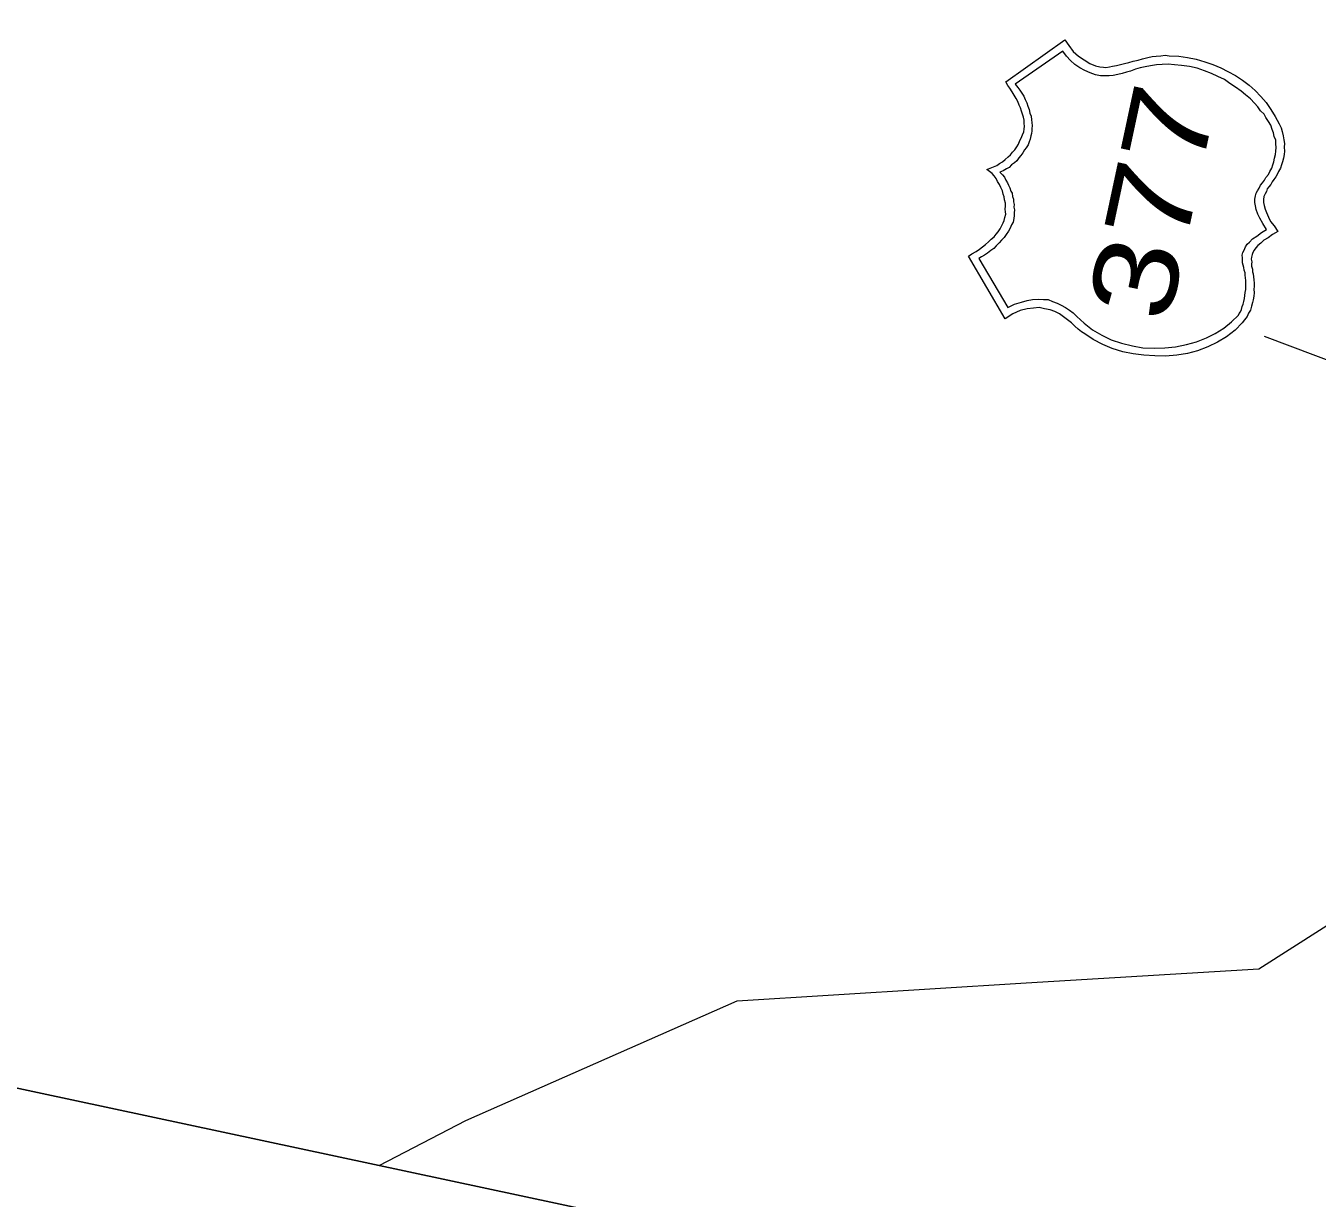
# Model space of a CAD drawing. Extents: x 2363411 to 2369126, y 6976878 to 6988319.
# Drawn here: x 2368295.3 to 2368374.1, y 6987786.2 to 6987857.8 of the extents above; entities that cross this region are included whole.
import ezdxf

# ---------------------------------------------------------------- set-up
doc = ezdxf.new("R2010")
doc.units = 0
doc.header["$LTSCALE"] = 2
doc.layers.add('62', color=7, linetype='Continuous', lineweight=13)
doc.layers.add('63', color=7, linetype='Continuous', lineweight=13)

msp = doc.modelspace()

# ---------------------------------------------------------------- linework, layer by layer
at = {"layer": '62', "lineweight": 25}
msp.add_lwpolyline([(2368004.774, 6987854.862), (2368459.776, 6987757.642), (2368553.719, 6988197.31), (2368098.715, 6988294.53)], dxfattribs=at)
at = {"layer": '62'}
for points in [[(2368355.078, 6987839.909), (2368352.834, 6987843.724), (2368353.048, 6987843.863), (2368353.31, 6987844.013), (2368353.501, 6987844.157), (2368353.694, 6987844.299), (2368353.885, 6987844.443), (2368354.06, 6987844.614), (2368354.228, 6987844.762), (2368354.4, 6987844.909), (2368354.525, 6987845.067), (2368354.649, 6987845.224), (2368354.779, 6987845.401), (2368354.861, 6987845.57), (2368354.947, 6987845.758), (2368355.023, 6987845.903), (2368355.067, 6987846.1), (2368355.109, 6987846.298), (2368355.093, 6987846.44), (2368355.082, 6987846.604), (2368355.097, 6987846.785), (2368355.092, 6987846.97), (2368355.041, 6987847.165), (2368355.012, 6987847.355), (2368354.959, 6987847.526), (2368354.909, 6987847.721), (2368354.813, 6987847.928), (2368354.735, 6987848.106), (2368354.614, 6987848.291), (2368354.537, 6987848.469), (2368354.413, 6987848.635), (2368354.281, 6987848.776), (2368354.125, 6987848.901), (2368353.967, 6987849.029), (2368354.167, 6987849.1), (2368354.37, 6987849.194), (2368354.57, 6987849.266), (2368354.736, 6987849.394), (2368354.919, 6987849.492), (2368355.086, 6987849.64), (2368355.258, 6987849.788), (2368355.4, 6987849.917), (2368355.524, 6987850.076), (2368355.674, 6987850.231), (2368355.781, 6987850.414), (2368355.886, 6987850.574), (2368355.976, 6987850.788), (2368356.054, 6987850.931), (2368356.143, 6987851.141), (2368356.209, 6987851.333), (2368356.241, 6987851.488), (2368356.256, 6987851.667), (2368356.247, 6987851.83), (2368356.245, 6987852.041), (2368356.189, 6987852.213), (2368356.139, 6987852.407), (2368356.083, 6987852.581), (2368356.01, 6987852.781), (2368355.933, 6987852.957), (2368355.844, 6987853.184), (2368355.745, 6987853.367), (2368355.629, 6987853.574), (2368355.507, 6987853.763), (2368355.373, 6987853.997), (2368355.249, 6987854.162), (2368355.11, 6987854.376), (2368358.717, 6987856.943), (2368358.965, 6987856.589), (2368359.233, 6987856.233), (2368359.565, 6987855.954), (2368359.907, 6987855.721), (2368360.254, 6987855.508), (2368360.591, 6987855.366), (2368360.851, 6987855.288), (2368361.075, 6987855.265), (2368361.234, 6987855.254), (2368361.452, 6987855.299), (2368361.639, 6987855.327), (2368361.881, 6987855.367), (2368362.127, 6987855.431), (2368362.369, 6987855.496), (2368362.634, 6987855.554), (2368362.904, 6987855.633), (2368363.198, 6987855.707), (2368363.467, 6987855.789), (2368363.783, 6987855.858), (2368364.047, 6987855.917), (2368364.307, 6987855.953), (2368364.585, 6987855.963), (2368364.848, 6987855.999), (2368365.095, 6987855.969), (2368365.684, 6987855.937), (2368366.222, 6987855.867), (2368366.749, 6987855.754), (2368367.268, 6987855.596), (2368367.766, 6987855.445), (2368368.247, 6987855.226), (2368368.684, 6987855.018), (2368369.137, 6987854.759), (2368369.564, 6987854.486), (2368369.978, 6987854.167)], [(2368370.504, 6987852.858), (2368370.297, 6987853.086), (2368370.054, 6987853.345), (2368369.761, 6987853.591), (2368369.488, 6987853.811), (2368369.145, 6987854.046), (2368368.806, 6987854.28), (2368368.465, 6987854.512), (2368368.068, 6987854.714), (2368367.67, 6987854.891), (2368367.243, 6987855.05), (2368366.795, 6987855.215), (2368366.333, 6987855.312), (2368365.84, 6987855.374), (2368365.412, 6987855.416), (2368365.03, 6987855.455), (2368364.659, 6987855.442), (2368364.311, 6987855.425), (2368363.953, 6987855.364), (2368363.637, 6987855.292), (2368363.327, 6987855.242), (2368363.03, 6987855.146), (2368362.729, 6987855.026), (2368362.487, 6987854.961), (2368362.216, 6987854.882), (2368361.95, 6987854.825), (2368361.684, 6987854.765), (2368361.426, 6987854.753), (2368361.17, 6987854.738), (2368360.896, 6987854.749), (2368360.588, 6987854.815), (2368360.266, 6987854.931), (2368359.951, 6987855.068), (2368359.639, 6987855.226), (2368359.339, 6987855.43), (2368359.073, 6987855.691), (2368358.828, 6987855.952), (2368358.595, 6987856.255), (2368355.699, 6987854.227), (2368355.842, 6987854.035), (2368355.969, 6987853.869), (2368356.089, 6987853.684), (2368356.21, 6987853.497), (2368356.306, 6987853.294), (2368356.4, 6987853.088), (2368356.471, 6987852.891), (2368356.543, 6987852.689), (2368356.589, 6987852.473), (2368356.661, 6987852.273), (2368356.686, 6987852.059), (2368356.698, 6987851.897), (2368356.72, 6987851.686), (2368356.71, 6987851.527), (2368356.703, 6987851.389), (2368356.691, 6987851.23), (2368356.639, 6987851.082), (2368356.596, 6987850.882), (2368356.535, 6987850.711), (2368356.475, 6987850.54), (2368356.368, 6987850.356), (2368356.268, 6987850.216), (2368356.159, 6987850.033), (2368356.034, 6987849.876), (2368355.913, 6987849.74), (2368355.782, 6987849.559), (2368355.64, 6987849.43), (2368355.475, 6987849.304), (2368355.327, 6987849.151), (2368355.15, 6987849.075), (2368354.964, 6987848.953), (2368354.76, 6987848.857), (2368354.907, 6987848.689), (2368355.037, 6987848.547), (2368355.115, 6987848.368), (2368355.219, 6987848.209), (2368355.277, 6987848.058), (2368355.359, 6987847.903), (2368355.432, 6987847.701), (2368355.496, 6987847.571), (2368355.524, 6987847.383), (2368355.579, 6987847.21), (2368355.593, 6987847.047), (2368355.624, 6987846.879), (2368355.612, 6987846.718), (2368355.647, 6987846.553), (2368355.633, 6987846.372), (2368355.621, 6987846.213), (2368355.604, 6987846.033), (2368355.557, 6987845.812), (2368355.475, 6987845.645), (2368355.384, 6987845.435), (2368355.277, 6987845.252), (2368355.141, 6987845.049), (2368355.011, 6987844.871), (2368354.863, 6987844.718), (2368354.71, 6987844.542), (2368354.533, 6987844.353), (2368354.384, 6987844.199), (2368354.198, 6987844.077), (2368354.001, 6987843.913), (2368353.815, 6987843.791)], [(2368369.978, 6987854.167), (2368370.35, 6987853.858), (2368370.683, 6987853.486), (2368371.018, 6987853.118), (2368371.294, 6987852.689), (2368371.571, 6987852.262), (2368371.822, 6987851.817), (2368371.929, 6987851.563), (2368371.996, 6987851.343), (2368372.054, 6987851.077), (2368372.097, 6987850.838), (2368372.141, 6987850.622), (2368372.115, 6987850.397), (2368372.13, 6987850.14), (2368372.111, 6987849.937), (2368372.085, 6987849.714), (2368372.017, 6987849.497), (2368371.952, 6987849.305), (2368371.888, 6987849.112), (2368371.774, 6987848.905), (2368371.72, 6987848.755), (2368371.613, 6987848.571), (2368371.485, 6987848.415), (2368371.386, 6987848.274), (2368371.307, 6987848.109), (2368371.186, 6987847.974), (2368371.087, 6987847.835), (2368371.031, 6987847.684), (2368370.954, 6987847.538), (2368370.872, 6987847.372), (2368370.856, 6987847.191), (2368370.862, 6987847.006), (2368370.89, 6987846.816), (2368370.958, 6987846.593), (2368371.032, 6987846.393), (2368371.156, 6987846.115), (2368371.284, 6987845.856), (2368371.502, 6987845.581), (2368371.726, 6987845.232), (2368371.412, 6987845.048), (2368371.139, 6987844.852), (2368370.878, 6987844.702), (2368370.702, 6987844.531), (2368370.51, 6987844.388), (2368370.385, 6987844.232), (2368370.286, 6987844.092), (2368370.209, 6987843.947), (2368370.163, 6987843.842), (2368370.125, 6987843.666), (2368370.103, 6987843.554), (2368370.135, 6987843.388), (2368370.13, 6987843.25), (2368370.123, 6987843.114), (2368370.178, 6987842.943), (2368370.188, 6987842.775), (2368370.232, 6987842.653), (2368370.237, 6987842.468), (2368370.268, 6987842.278), (2368370.295, 6987842.09), (2368370.276, 6987841.885), (2368370.258, 6987841.705), (2368370.282, 6987841.491), (2368370.262, 6987841.291), (2368370.217, 6987841.07), (2368370.177, 6987840.894), (2368370.13, 6987840.673), (2368370.058, 6987840.435), (2368369.948, 6987840.252), (2368369.858, 6987840.042), (2368369.701, 6987839.844), (2368369.545, 6987839.649), (2368369.128, 6987839.208), (2368368.603, 6987838.813), (2368368.05, 6987838.471), (2368367.459, 6987838.184), (2368366.834, 6987837.95), (2368366.223, 6987837.781), (2368365.559, 6987837.692), (2368364.88, 6987837.631), (2368364.213, 6987837.636), (2368363.557, 6987837.682), (2368362.903, 6987837.755), (2368362.265, 6987837.891), (2368361.62, 6987838.096), (2368361.049, 6987838.335), (2368360.449, 6987838.647), (2368359.945, 6987838.982), (2368359.746, 6987839.118), (2368359.527, 6987839.28), (2368359.335, 6987839.458), (2368359.126, 6987839.666), (2368358.884, 6987839.832), (2368358.648, 6987840.02), (2368358.389, 6987840.214), (2368358.118, 6987840.342), (2368357.817, 6987840.451), (2368357.488, 6987840.521), (2368357.157, 6987840.594), (2368356.803, 6987840.553), (2368356.426, 6987840.519), (2368355.99, 6987840.404)], [(2368353.472, 6987843.59), (2368355.245, 6987840.587), (2368355.658, 6987840.798), (2368356.076, 6987840.915), (2368356.423, 6987841.025), (2368356.757, 6987841.093), (2368357.106, 6987841.11), (2368357.424, 6987841.087), (2368357.698, 6987841.075), (2368357.976, 6987840.971), (2368358.252, 6987840.865), (2368358.502, 6987840.742), (2368358.772, 6987840.592), (2368359.011, 6987840.427), (2368359.23, 6987840.264), (2368359.461, 6987840.053), (2368359.67, 6987839.85), (2368359.901, 6987839.638), (2368360.414, 6987839.229), (2368360.986, 6987838.901), (2368361.548, 6987838.619), (2368362.192, 6987838.412), (2368362.847, 6987838.249), (2368363.493, 6987838.134), (2368364.174, 6987838.103), (2368364.823, 6987838.124), (2368365.481, 6987838.192), (2368366.155, 6987838.326), (2368366.766, 6987838.492), (2368367.37, 6987838.733), (2368367.911, 6987839.008), (2368368.44, 6987839.33), (2368368.891, 6987839.721), (2368369.325, 6987840.131), (2368369.37, 6987840.238), (2368369.46, 6987840.335), (2368369.514, 6987840.481), (2368369.554, 6987840.659), (2368369.608, 6987840.807), (2368369.662, 6987840.957), (2368369.7, 6987841.135), (2368369.719, 6987841.335), (2368369.736, 6987841.518), (2368369.773, 6987841.692), (2368369.767, 6987841.879), (2368369.782, 6987842.058), (2368369.776, 6987842.244), (2368369.764, 6987842.408), (2368369.732, 6987842.576), (2368369.739, 6987842.712), (2368369.682, 6987842.885), (2368369.645, 6987843.032), (2368369.608, 6987843.177), (2368369.571, 6987843.324), (2368369.564, 6987843.51), (2368369.564, 6987843.624), (2368369.554, 6987843.788), (2368369.592, 6987843.964), (2368369.667, 6987844.107), (2368369.755, 6987844.297), (2368369.859, 6987844.459), (2368370.001, 6987844.59), (2368370.18, 6987844.783), (2368370.448, 6987844.955), (2368370.723, 6987845.17), (2368371.038, 6987845.357), (2368370.819, 6987845.727), (2368370.633, 6987846.042), (2368370.504, 6987846.299), (2368370.402, 6987846.574), (2368370.361, 6987846.812), (2368370.333, 6987847.002), (2368370.332, 6987847.211), (2368370.373, 6987847.409), (2368370.411, 6987847.587), (2368370.488, 6987847.73), (2368370.592, 6987847.892), (2368370.673, 6987848.059), (2368370.799, 6987848.216), (2368370.926, 6987848.373), (2368371.006, 6987848.54), (2368371.159, 6987848.714), (2368371.244, 6987848.904), (2368371.36, 6987849.11), (2368371.424, 6987849.303), (2368371.487, 6987849.494), (2368371.533, 6987849.715), (2368371.581, 6987849.936), (2368371.603, 6987850.14), (2368371.626, 6987850.364), (2368371.608, 6987850.597), (2368371.606, 6987850.806), (2368371.515, 6987851.032), (2368371.474, 6987851.27), (2368371.381, 6987851.476), (2368371.296, 6987851.723), (2368371.161, 6987851.959), (2368371.007, 6987852.198), (2368370.889, 6987852.409), (2368370.68, 6987852.616), (2368370.504, 6987852.858)], [(2368316.854, 6987788.182), (2368322.138, 6987790.941), (2368338.721, 6987798.237), (2368356.354, 6987799.347), (2368370.57, 6987800.198), (2368380.507, 6987806.541), (2368397.068, 6987818.558), (2368405.207, 6987825.955), (2368418.347, 6987837.711), (2368437.149, 6987845.475)], [(2368353.815, 6987843.791), (2368353.632, 6987843.693), (2368353.472, 6987843.59)], [(2368355.99, 6987840.404), (2368355.554, 6987840.2), (2368355.078, 6987839.909)], [(2368370.893, 6987838.853), (2368383.263, 6987834.188), (2368395.397, 6987828.188), (2368404.391, 6987814.277), (2368413.364, 6987797.381), (2368426.436, 6987777.677), (2368432.622, 6987763.444)]]:
    msp.add_lwpolyline(points, dxfattribs=at)
at = {"layer": '63', "lineweight": 25}
msp.add_lwpolyline([(2368004.774, 6987854.862), (2368459.776, 6987757.642), (2368553.719, 6988197.31), (2368098.715, 6988294.53)], dxfattribs=at)
at = {"layer": '63'}
for points in [[(2368355.078, 6987839.909), (2368352.834, 6987843.724), (2368353.048, 6987843.863), (2368353.31, 6987844.013), (2368353.501, 6987844.157), (2368353.694, 6987844.299), (2368353.885, 6987844.443), (2368354.06, 6987844.614), (2368354.228, 6987844.762), (2368354.4, 6987844.909), (2368354.525, 6987845.067), (2368354.649, 6987845.224), (2368354.779, 6987845.401), (2368354.861, 6987845.57), (2368354.947, 6987845.758), (2368355.023, 6987845.903), (2368355.067, 6987846.1), (2368355.109, 6987846.298), (2368355.093, 6987846.44), (2368355.082, 6987846.604), (2368355.097, 6987846.785), (2368355.092, 6987846.97), (2368355.041, 6987847.165), (2368355.012, 6987847.355), (2368354.959, 6987847.526), (2368354.909, 6987847.721), (2368354.813, 6987847.928), (2368354.735, 6987848.106), (2368354.614, 6987848.291), (2368354.537, 6987848.469), (2368354.413, 6987848.635), (2368354.281, 6987848.776), (2368354.125, 6987848.901), (2368353.967, 6987849.029), (2368354.167, 6987849.1), (2368354.37, 6987849.194), (2368354.57, 6987849.266), (2368354.736, 6987849.394), (2368354.919, 6987849.492), (2368355.086, 6987849.64), (2368355.258, 6987849.788), (2368355.4, 6987849.917), (2368355.524, 6987850.076), (2368355.674, 6987850.231), (2368355.781, 6987850.414), (2368355.886, 6987850.574), (2368355.976, 6987850.788), (2368356.054, 6987850.931), (2368356.143, 6987851.141), (2368356.209, 6987851.333), (2368356.241, 6987851.488), (2368356.256, 6987851.667), (2368356.247, 6987851.83), (2368356.245, 6987852.041), (2368356.189, 6987852.213), (2368356.139, 6987852.407), (2368356.083, 6987852.581), (2368356.01, 6987852.781), (2368355.933, 6987852.957), (2368355.844, 6987853.184), (2368355.745, 6987853.367), (2368355.629, 6987853.574), (2368355.507, 6987853.763), (2368355.373, 6987853.997), (2368355.249, 6987854.162), (2368355.11, 6987854.376), (2368358.717, 6987856.943), (2368358.965, 6987856.589), (2368359.233, 6987856.233), (2368359.565, 6987855.954), (2368359.907, 6987855.721), (2368360.254, 6987855.508), (2368360.591, 6987855.366), (2368360.851, 6987855.288), (2368361.075, 6987855.265), (2368361.234, 6987855.254), (2368361.452, 6987855.299), (2368361.639, 6987855.327), (2368361.881, 6987855.367), (2368362.127, 6987855.431), (2368362.369, 6987855.496), (2368362.634, 6987855.554), (2368362.904, 6987855.633), (2368363.198, 6987855.707), (2368363.467, 6987855.789), (2368363.783, 6987855.858), (2368364.047, 6987855.917), (2368364.307, 6987855.953), (2368364.585, 6987855.963), (2368364.848, 6987855.999), (2368365.095, 6987855.969), (2368365.684, 6987855.937), (2368366.222, 6987855.867), (2368366.749, 6987855.754), (2368367.268, 6987855.596), (2368367.766, 6987855.445), (2368368.247, 6987855.226), (2368368.684, 6987855.018), (2368369.137, 6987854.759), (2368369.564, 6987854.486), (2368369.978, 6987854.167)], [(2368370.504, 6987852.858), (2368370.297, 6987853.086), (2368370.054, 6987853.345), (2368369.761, 6987853.591), (2368369.488, 6987853.811), (2368369.145, 6987854.046), (2368368.806, 6987854.28), (2368368.465, 6987854.512), (2368368.068, 6987854.714), (2368367.67, 6987854.891), (2368367.243, 6987855.05), (2368366.795, 6987855.215), (2368366.333, 6987855.312), (2368365.84, 6987855.374), (2368365.412, 6987855.416), (2368365.03, 6987855.455), (2368364.659, 6987855.442), (2368364.311, 6987855.425), (2368363.953, 6987855.364), (2368363.637, 6987855.292), (2368363.327, 6987855.242), (2368363.03, 6987855.146), (2368362.729, 6987855.026), (2368362.487, 6987854.961), (2368362.216, 6987854.882), (2368361.95, 6987854.825), (2368361.684, 6987854.765), (2368361.426, 6987854.753), (2368361.17, 6987854.738), (2368360.896, 6987854.749), (2368360.588, 6987854.815), (2368360.266, 6987854.931), (2368359.951, 6987855.068), (2368359.639, 6987855.226), (2368359.339, 6987855.43), (2368359.073, 6987855.691), (2368358.828, 6987855.952), (2368358.595, 6987856.255), (2368355.699, 6987854.227), (2368355.842, 6987854.035), (2368355.969, 6987853.869), (2368356.089, 6987853.684), (2368356.21, 6987853.497), (2368356.306, 6987853.294), (2368356.4, 6987853.088), (2368356.471, 6987852.891), (2368356.543, 6987852.689), (2368356.589, 6987852.473), (2368356.661, 6987852.273), (2368356.686, 6987852.059), (2368356.698, 6987851.897), (2368356.72, 6987851.686), (2368356.71, 6987851.527), (2368356.703, 6987851.389), (2368356.691, 6987851.23), (2368356.639, 6987851.082), (2368356.596, 6987850.882), (2368356.535, 6987850.711), (2368356.475, 6987850.54), (2368356.368, 6987850.356), (2368356.268, 6987850.216), (2368356.159, 6987850.033), (2368356.034, 6987849.876), (2368355.913, 6987849.74), (2368355.782, 6987849.559), (2368355.64, 6987849.43), (2368355.475, 6987849.304), (2368355.327, 6987849.151), (2368355.15, 6987849.075), (2368354.964, 6987848.953), (2368354.76, 6987848.857), (2368354.907, 6987848.689), (2368355.037, 6987848.547), (2368355.115, 6987848.368), (2368355.219, 6987848.209), (2368355.277, 6987848.058), (2368355.359, 6987847.903), (2368355.432, 6987847.701), (2368355.496, 6987847.571), (2368355.524, 6987847.383), (2368355.579, 6987847.21), (2368355.593, 6987847.047), (2368355.624, 6987846.879), (2368355.612, 6987846.718), (2368355.647, 6987846.553), (2368355.633, 6987846.372), (2368355.621, 6987846.213), (2368355.604, 6987846.033), (2368355.557, 6987845.812), (2368355.475, 6987845.645), (2368355.384, 6987845.435), (2368355.277, 6987845.252), (2368355.141, 6987845.049), (2368355.011, 6987844.871), (2368354.863, 6987844.718), (2368354.71, 6987844.542), (2368354.533, 6987844.353), (2368354.384, 6987844.199), (2368354.198, 6987844.077), (2368354.001, 6987843.913), (2368353.815, 6987843.791)], [(2368369.978, 6987854.167), (2368370.35, 6987853.858), (2368370.683, 6987853.486), (2368371.018, 6987853.118), (2368371.294, 6987852.689), (2368371.571, 6987852.262), (2368371.822, 6987851.817), (2368371.929, 6987851.563), (2368371.996, 6987851.343), (2368372.054, 6987851.077), (2368372.097, 6987850.838), (2368372.141, 6987850.622), (2368372.115, 6987850.397), (2368372.13, 6987850.14), (2368372.111, 6987849.937), (2368372.085, 6987849.714), (2368372.017, 6987849.497), (2368371.952, 6987849.305), (2368371.888, 6987849.112), (2368371.774, 6987848.905), (2368371.72, 6987848.755), (2368371.613, 6987848.571), (2368371.485, 6987848.415), (2368371.386, 6987848.274), (2368371.307, 6987848.109), (2368371.186, 6987847.974), (2368371.087, 6987847.835), (2368371.031, 6987847.684), (2368370.954, 6987847.538), (2368370.872, 6987847.372), (2368370.856, 6987847.191), (2368370.862, 6987847.006), (2368370.89, 6987846.816), (2368370.958, 6987846.593), (2368371.032, 6987846.393), (2368371.156, 6987846.115), (2368371.284, 6987845.856), (2368371.502, 6987845.581), (2368371.726, 6987845.232), (2368371.412, 6987845.048), (2368371.139, 6987844.852), (2368370.878, 6987844.702), (2368370.702, 6987844.531), (2368370.51, 6987844.388), (2368370.385, 6987844.232), (2368370.286, 6987844.092), (2368370.209, 6987843.947), (2368370.163, 6987843.842), (2368370.125, 6987843.666), (2368370.103, 6987843.554), (2368370.135, 6987843.388), (2368370.13, 6987843.25), (2368370.123, 6987843.114), (2368370.178, 6987842.943), (2368370.188, 6987842.775), (2368370.232, 6987842.653), (2368370.237, 6987842.468), (2368370.268, 6987842.278), (2368370.295, 6987842.09), (2368370.276, 6987841.885), (2368370.258, 6987841.705), (2368370.282, 6987841.491), (2368370.262, 6987841.291), (2368370.217, 6987841.07), (2368370.177, 6987840.894), (2368370.13, 6987840.673), (2368370.058, 6987840.435), (2368369.948, 6987840.252), (2368369.858, 6987840.042), (2368369.701, 6987839.844), (2368369.545, 6987839.649), (2368369.128, 6987839.208), (2368368.603, 6987838.813), (2368368.05, 6987838.471), (2368367.459, 6987838.184), (2368366.834, 6987837.95), (2368366.223, 6987837.781), (2368365.559, 6987837.692), (2368364.88, 6987837.631), (2368364.213, 6987837.636), (2368363.557, 6987837.682), (2368362.903, 6987837.755), (2368362.265, 6987837.891), (2368361.62, 6987838.096), (2368361.049, 6987838.335), (2368360.449, 6987838.647), (2368359.945, 6987838.982), (2368359.746, 6987839.118), (2368359.527, 6987839.28), (2368359.335, 6987839.458), (2368359.126, 6987839.666), (2368358.884, 6987839.832), (2368358.648, 6987840.02), (2368358.389, 6987840.214), (2368358.118, 6987840.342), (2368357.817, 6987840.451), (2368357.488, 6987840.521), (2368357.157, 6987840.594), (2368356.803, 6987840.553), (2368356.426, 6987840.519), (2368355.99, 6987840.404)], [(2368353.472, 6987843.59), (2368355.245, 6987840.587), (2368355.658, 6987840.798), (2368356.076, 6987840.915), (2368356.423, 6987841.025), (2368356.757, 6987841.093), (2368357.106, 6987841.11), (2368357.424, 6987841.087), (2368357.698, 6987841.075), (2368357.976, 6987840.971), (2368358.252, 6987840.865), (2368358.502, 6987840.742), (2368358.772, 6987840.592), (2368359.011, 6987840.427), (2368359.23, 6987840.264), (2368359.461, 6987840.053), (2368359.67, 6987839.85), (2368359.901, 6987839.638), (2368360.414, 6987839.229), (2368360.986, 6987838.901), (2368361.548, 6987838.619), (2368362.192, 6987838.412), (2368362.847, 6987838.249), (2368363.493, 6987838.134), (2368364.174, 6987838.103), (2368364.823, 6987838.124), (2368365.481, 6987838.192), (2368366.155, 6987838.326), (2368366.766, 6987838.492), (2368367.37, 6987838.733), (2368367.911, 6987839.008), (2368368.44, 6987839.33), (2368368.891, 6987839.721), (2368369.325, 6987840.131), (2368369.37, 6987840.238), (2368369.46, 6987840.335), (2368369.514, 6987840.481), (2368369.554, 6987840.659), (2368369.608, 6987840.807), (2368369.662, 6987840.957), (2368369.7, 6987841.135), (2368369.719, 6987841.335), (2368369.736, 6987841.518), (2368369.773, 6987841.692), (2368369.767, 6987841.879), (2368369.782, 6987842.058), (2368369.776, 6987842.244), (2368369.764, 6987842.408), (2368369.732, 6987842.576), (2368369.739, 6987842.712), (2368369.682, 6987842.885), (2368369.645, 6987843.032), (2368369.608, 6987843.177), (2368369.571, 6987843.324), (2368369.564, 6987843.51), (2368369.564, 6987843.624), (2368369.554, 6987843.788), (2368369.592, 6987843.964), (2368369.667, 6987844.107), (2368369.755, 6987844.297), (2368369.859, 6987844.459), (2368370.001, 6987844.59), (2368370.18, 6987844.783), (2368370.448, 6987844.955), (2368370.723, 6987845.17), (2368371.038, 6987845.357), (2368370.819, 6987845.727), (2368370.633, 6987846.042), (2368370.504, 6987846.299), (2368370.402, 6987846.574), (2368370.361, 6987846.812), (2368370.333, 6987847.002), (2368370.332, 6987847.211), (2368370.373, 6987847.409), (2368370.411, 6987847.587), (2368370.488, 6987847.73), (2368370.592, 6987847.892), (2368370.673, 6987848.059), (2368370.799, 6987848.216), (2368370.926, 6987848.373), (2368371.006, 6987848.54), (2368371.159, 6987848.714), (2368371.244, 6987848.904), (2368371.36, 6987849.11), (2368371.424, 6987849.303), (2368371.487, 6987849.494), (2368371.533, 6987849.715), (2368371.581, 6987849.936), (2368371.603, 6987850.14), (2368371.626, 6987850.364), (2368371.608, 6987850.597), (2368371.606, 6987850.806), (2368371.515, 6987851.032), (2368371.474, 6987851.27), (2368371.381, 6987851.476), (2368371.296, 6987851.723), (2368371.161, 6987851.959), (2368371.007, 6987852.198), (2368370.889, 6987852.409), (2368370.68, 6987852.616), (2368370.504, 6987852.858)], [(2368316.854, 6987788.182), (2368322.138, 6987790.941), (2368338.721, 6987798.237), (2368356.354, 6987799.347), (2368370.57, 6987800.198), (2368380.507, 6987806.541), (2368397.068, 6987818.558), (2368405.207, 6987825.955), (2368418.347, 6987837.711), (2368437.149, 6987845.475)], [(2368353.815, 6987843.791), (2368353.632, 6987843.693), (2368353.472, 6987843.59)], [(2368355.99, 6987840.404), (2368355.554, 6987840.2), (2368355.078, 6987839.909)], [(2368370.893, 6987838.853), (2368383.263, 6987834.188), (2368395.397, 6987828.188), (2368404.391, 6987814.277), (2368413.364, 6987797.381), (2368426.436, 6987777.677), (2368432.622, 6987763.444)]]:
    msp.add_lwpolyline(points, dxfattribs=at)

# ---------------------------------------------------------------- texts
at = {"layer": '62', "width": 1.25}
msp.add_text('377', height=5.099, rotation=77.939, dxfattribs=at).set_placement((2368365.06, 6987839.549))
at = {"layer": '63', "width": 1.25}
msp.add_text('377', height=5.099, rotation=77.939, dxfattribs=at).set_placement((2368365.06, 6987839.549))

doc.saveas('drawing.dxf')
